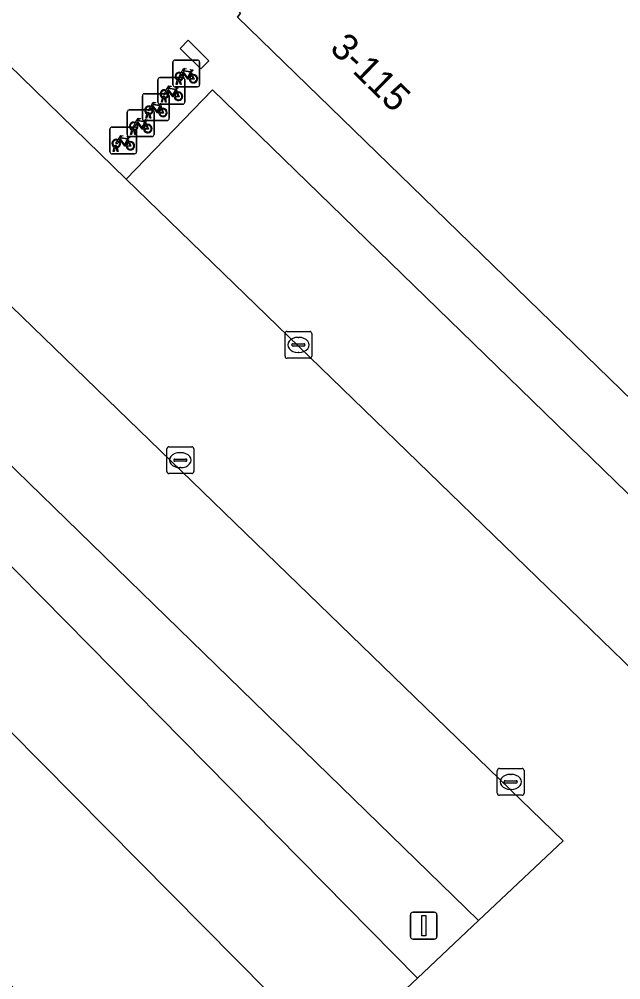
# Model space of a CAD drawing. Extents: x 162344 to 162869, y 381217 to 381818.
# Drawn here: x 162731.05 to 162753.52, y 381504.82 to 381540.68 of the extents above; entities that cross this region are included whole.
import ezdxf

# ---------------------------------------------------------------- set-up
doc = ezdxf.new("R2010")
doc.units = 0
for name, color, linetype in [('IMGEO_Erf', 7, 'Continuous'), ('IMGEO_Fietsenrek', 7, 'Continuous'), ('IMGEO_Groenvoorziening', 7, 'Continuous'), ('IMGEO_Kolk', 7, 'Continuous'), ('IMGEO_Lichtmast', 7, 'Continuous'), ('IMGEO_Pand', 7, 'Continuous'), ('IMGEO_Pand_nummerreeks', 7, 'Continuous'), ('IMGEO_Parkeervlak_open', 7, 'Continuous'), ('IMGEO_Rijbaan_lokaal_open', 7, 'Continuous')]:
    doc.layers.add(name, color=color, linetype=linetype)

msp = doc.modelspace()

# ---------------------------------------------------------------- linework, layer by layer
at = {"layer": 'IMGEO_Erf'}
for points in [[(162701.58, 381592.223), (162697.423, 381587.94), (162694.297, 381584.72), (162697.845, 381581.274), (162694.262, 381577.583), (162691.765, 381574.889), (162691.764, 381574.604), (162695.157, 381571.045), (162696.402, 381572.245), (162698.843, 381569.907), (162702.056, 381573.223), (162726.23, 381549.751), (162723.009, 381546.422), (162723.525, 381545.93), (162729.038, 381540.567), (162729.149, 381540.721), (162730.76, 381539.135), (162730.657, 381538.992), (162735.052, 381534.717), (162738.275, 381538.047), (162760.834, 381516.121)], [(162802.337, 381472.727), (162763.915, 381510.041), (162763.999, 381510.127), (162762.508, 381511.578), (162764.591, 381513.721), (162764.908, 381513.413), (162766.104, 381514.636), (162739.201, 381540.759), (162739.317, 381540.907), (162736.543, 381543.625), (162731.819, 381548.213), (162729.043, 381550.887), (162728.906, 381550.749), (162701.975, 381576.843), (162700.092, 381574.95), (162698.199, 381576.833), (162698.296, 381576.933), (162696.8, 381578.375), (162698.869, 381580.518), (162699.221, 381580.178), (162699.971, 381580.954), (162703.019, 381584.107), (162701.127, 381585.931), (162705.36, 381590.307)]]:
    msp.add_lwpolyline(points, dxfattribs=at)
msp.add_lwpolyline([(162738.136, 381539.135), (162737.841, 381538.836), (162737.069, 381539.597), (162737.358, 381539.902)], close=True, dxfattribs=at)
at = {"layer": 'IMGEO_Fietsenrek'}
for p, q in [((162736.791, 381538.237), (162736.791, 381539.078)), ((162736.791, 381539.078), (162736.791, 381538.237)), ((162736.866, 381539.162), (162737.707, 381539.162)), ((162737.707, 381539.162), (162736.866, 381539.162)), ((162737.791, 381539.087), (162737.791, 381538.246)), ((162737.791, 381538.246), (162737.791, 381539.087)), ((162736.308, 381538.508), (162737.149, 381538.508)), ((162737.149, 381538.508), (162736.308, 381538.508)), ((162737.478, 381538.711), (162737.514, 381538.616)), ((162736.233, 381537.583), (162736.233, 381538.424)), ((162736.233, 381538.424), (162736.233, 381537.583)), ((162737.716, 381538.162), (162736.875, 381538.162)), ((162736.875, 381538.162), (162737.716, 381538.162)), ((162736.918, 381538.246), (162736.957, 381538.406)), ((162736.952, 381538.246), (162736.918, 381538.246)), ((162736.987, 381538.394), (162736.952, 381538.246)), ((162737.029, 381538.418), (162737.028, 381538.422)), ((162737.07, 381538.246), (162737.036, 381538.388)), ((162737.06, 381538.429), (162737.061, 381538.422)), ((162737.068, 381538.392), (162737.103, 381538.246)), ((162737.103, 381538.246), (162737.07, 381538.246)), ((162737.233, 381538.433), (162737.233, 381537.592)), ((162737.233, 381537.592), (162737.233, 381538.433)), ((162735.652, 381536.977), (162735.652, 381537.818)), ((162735.652, 381537.818), (162735.652, 381536.977)), ((162735.727, 381537.902), (162736.568, 381537.902)), ((162736.568, 381537.902), (162735.727, 381537.902)), ((162736.36, 381537.592), (162736.399, 381537.752)), ((162736.429, 381537.74), (162736.394, 381537.592)), ((162736.471, 381537.764), (162736.47, 381537.768)), ((162736.512, 381537.592), (162736.478, 381537.734)), ((162736.502, 381537.775), (162736.503, 381537.768)), ((162736.51, 381537.738), (162736.545, 381537.592)), ((162736.652, 381537.827), (162736.652, 381536.986)), ((162736.652, 381536.986), (162736.652, 381537.827)), ((162736.92, 381538.057), (162736.956, 381537.962)), ((162737.158, 381537.508), (162736.317, 381537.508)), ((162736.317, 381537.508), (162737.158, 381537.508)), ((162736.339, 381537.451), (162736.375, 381537.356)), ((162736.394, 381537.592), (162736.36, 381537.592)), ((162736.545, 381537.592), (162736.512, 381537.592)), ((162735.087, 381536.376), (162735.087, 381537.217)), ((162735.087, 381537.217), (162735.087, 381536.376)), ((162735.162, 381537.301), (162736.003, 381537.301)), ((162736.003, 381537.301), (162735.162, 381537.301)), ((162735.779, 381536.986), (162735.818, 381537.146)), ((162735.848, 381537.134), (162735.813, 381536.986)), ((162735.89, 381537.158), (162735.889, 381537.162)), ((162735.931, 381536.986), (162735.897, 381537.128)), ((162735.921, 381537.169), (162735.922, 381537.162)), ((162735.929, 381537.132), (162735.964, 381536.986)), ((162736.087, 381537.226), (162736.087, 381536.385)), ((162736.087, 381536.385), (162736.087, 381537.226)), ((162734.511, 381536.659), (162735.352, 381536.659)), ((162735.352, 381536.659), (162734.511, 381536.659)), ((162736.577, 381536.902), (162735.736, 381536.902)), ((162735.736, 381536.902), (162736.577, 381536.902)), ((162735.774, 381536.85), (162735.81, 381536.755)), ((162735.813, 381536.986), (162735.779, 381536.986)), ((162735.964, 381536.986), (162735.931, 381536.986)), ((162734.436, 381535.734), (162734.436, 381536.575)), ((162734.436, 381536.575), (162734.436, 381535.734)), ((162736.012, 381536.301), (162735.171, 381536.301)), ((162735.171, 381536.301), (162736.012, 381536.301)), ((162735.214, 381536.385), (162735.253, 381536.545)), ((162735.248, 381536.385), (162735.214, 381536.385)), ((162735.283, 381536.533), (162735.248, 381536.385)), ((162735.325, 381536.557), (162735.324, 381536.561)), ((162735.366, 381536.385), (162735.332, 381536.527)), ((162735.356, 381536.568), (162735.357, 381536.561)), ((162735.364, 381536.531), (162735.399, 381536.385)), ((162735.399, 381536.385), (162735.366, 381536.385)), ((162735.436, 381536.584), (162735.436, 381535.743)), ((162735.436, 381535.743), (162735.436, 381536.584)), ((162735.123, 381536.208), (162735.159, 381536.113)), ((162735.361, 381535.659), (162734.52, 381535.659)), ((162734.52, 381535.659), (162735.361, 381535.659)), ((162734.563, 381535.743), (162734.602, 381535.903)), ((162734.597, 381535.743), (162734.563, 381535.743)), ((162734.632, 381535.891), (162734.597, 381535.743)), ((162734.674, 381535.915), (162734.673, 381535.919)), ((162734.715, 381535.743), (162734.681, 381535.885)), ((162734.705, 381535.926), (162734.706, 381535.919)), ((162734.713, 381535.889), (162734.748, 381535.743)), ((162734.748, 381535.743), (162734.715, 381535.743))]:
    msp.add_line(p, q, dxfattribs=at)
for points in [[(162737.104, 381538.688), (162737.199, 381538.852), (162737.285, 381538.838), (162737.287, 381538.829), (162737.231, 381538.818), (162737.204, 381538.773), (162737.46, 381538.732)], [(162737.46, 381538.732), (162737.485, 381538.781), (162737.479, 381538.785), (162737.456, 381538.789), (162737.444, 381538.796), (162737.443, 381538.799), (162737.445, 381538.804), (162737.54, 381538.789), (162737.542, 381538.779), (162737.532, 381538.766), (162737.52, 381538.76), (162737.506, 381538.766), (162737.478, 381538.711)], [(162737.125, 381538.636), (162737.073, 381538.546), (162737.033, 381538.521), (162737.034, 381538.568), (162737.089, 381538.662)], [(162737.4, 381538.444), (162737.35, 381538.444), (162737.159, 381538.695), (162737.14, 381538.663)], [(162737.447, 381538.707), (162737.19, 381538.748), (162737.173, 381538.719), (162737.34, 381538.499), (162737.447, 381538.707)], [(162737.495, 381538.609), (162737.465, 381538.686), (162737.356, 381538.468), (162737.399, 381538.468)], [(162737.429, 381538.468), (162737.549, 381538.467), (162737.505, 381538.581)], [(162737.525, 381538.588), (162737.58, 381538.443), (162737.43, 381538.443)], [(162736.546, 381538.034), (162736.641, 381538.198), (162736.727, 381538.184), (162736.729, 381538.175), (162736.673, 381538.164), (162736.646, 381538.119), (162736.902, 381538.078)], [(162736.889, 381538.053), (162736.632, 381538.094), (162736.615, 381538.065), (162736.782, 381537.845), (162736.889, 381538.053)], [(162736.902, 381538.078), (162736.927, 381538.127), (162736.921, 381538.131), (162736.898, 381538.135), (162736.886, 381538.142), (162736.885, 381538.145), (162736.887, 381538.15), (162736.982, 381538.135), (162736.984, 381538.125), (162736.974, 381538.112), (162736.962, 381538.106), (162736.948, 381538.112), (162736.92, 381538.057)], [(162736.567, 381537.982), (162736.515, 381537.892), (162736.475, 381537.867), (162736.476, 381537.914), (162736.531, 381538.008)], [(162736.842, 381537.79), (162736.792, 381537.79), (162736.601, 381538.041), (162736.582, 381538.009)], [(162736.937, 381537.955), (162736.907, 381538.032), (162736.798, 381537.814), (162736.841, 381537.814)], [(162736.871, 381537.814), (162736.991, 381537.813), (162736.947, 381537.927)], [(162736.967, 381537.934), (162737.022, 381537.789), (162736.872, 381537.789)], [(162735.986, 381537.376), (162735.934, 381537.286), (162735.894, 381537.261), (162735.895, 381537.308), (162735.95, 381537.402)], [(162735.965, 381537.428), (162736.06, 381537.592), (162736.146, 381537.578), (162736.148, 381537.569), (162736.092, 381537.558), (162736.065, 381537.513), (162736.321, 381537.472)], [(162736.261, 381537.184), (162736.211, 381537.184), (162736.02, 381537.435), (162736.001, 381537.403)], [(162736.308, 381537.447), (162736.051, 381537.488), (162736.034, 381537.459), (162736.201, 381537.239), (162736.308, 381537.447)], [(162736.356, 381537.349), (162736.326, 381537.426), (162736.217, 381537.208), (162736.26, 381537.208)], [(162736.321, 381537.472), (162736.346, 381537.521), (162736.34, 381537.525), (162736.317, 381537.529), (162736.305, 381537.536), (162736.304, 381537.539), (162736.306, 381537.544), (162736.401, 381537.529), (162736.403, 381537.519), (162736.393, 381537.506), (162736.381, 381537.5), (162736.367, 381537.506), (162736.339, 381537.451)], [(162736.29, 381537.208), (162736.41, 381537.207), (162736.366, 381537.321)], [(162736.386, 381537.328), (162736.441, 381537.183), (162736.291, 381537.183)], [(162735.421, 381536.775), (162735.369, 381536.685), (162735.329, 381536.66), (162735.33, 381536.707), (162735.385, 381536.801)], [(162735.4, 381536.827), (162735.495, 381536.991), (162735.581, 381536.977), (162735.583, 381536.968), (162735.527, 381536.957), (162735.5, 381536.912), (162735.756, 381536.871)], [(162735.696, 381536.583), (162735.646, 381536.583), (162735.455, 381536.834), (162735.436, 381536.802)], [(162735.743, 381536.846), (162735.486, 381536.887), (162735.469, 381536.858), (162735.636, 381536.638), (162735.743, 381536.846)], [(162735.791, 381536.748), (162735.761, 381536.825), (162735.652, 381536.607), (162735.695, 381536.607)], [(162735.725, 381536.607), (162735.845, 381536.606), (162735.801, 381536.72)], [(162735.821, 381536.727), (162735.876, 381536.582), (162735.726, 381536.582)], [(162735.756, 381536.871), (162735.781, 381536.92), (162735.775, 381536.924), (162735.752, 381536.928), (162735.74, 381536.935), (162735.739, 381536.938), (162735.741, 381536.943), (162735.836, 381536.928), (162735.838, 381536.918), (162735.828, 381536.905), (162735.816, 381536.899), (162735.802, 381536.905), (162735.774, 381536.85)], [(162734.749, 381536.185), (162734.844, 381536.349), (162734.93, 381536.335), (162734.932, 381536.326), (162734.876, 381536.315), (162734.849, 381536.27), (162735.105, 381536.229)], [(162735.105, 381536.229), (162735.13, 381536.278), (162735.124, 381536.282), (162735.101, 381536.286), (162735.089, 381536.293), (162735.088, 381536.296), (162735.09, 381536.301), (162735.185, 381536.286), (162735.187, 381536.276), (162735.177, 381536.263), (162735.165, 381536.257), (162735.151, 381536.263), (162735.123, 381536.208)], [(162734.77, 381536.133), (162734.718, 381536.043), (162734.678, 381536.018), (162734.679, 381536.065), (162734.734, 381536.159)], [(162735.045, 381535.941), (162734.995, 381535.941), (162734.804, 381536.192), (162734.785, 381536.16)], [(162735.092, 381536.204), (162734.835, 381536.245), (162734.818, 381536.216), (162734.985, 381535.996), (162735.092, 381536.204)], [(162735.14, 381536.106), (162735.11, 381536.183), (162735.001, 381535.965), (162735.044, 381535.965)], [(162735.074, 381535.965), (162735.194, 381535.964), (162735.15, 381536.078)], [(162735.17, 381536.085), (162735.225, 381535.94), (162735.075, 381535.94)]]:
    msp.add_lwpolyline(points, dxfattribs=at)
for centre, radius, start, end in [((162736.869, 381539.084), 0.0779, 92.4484, 184.2845), ((162736.869, 381539.084), 0.0779, 92.4484, 184.2845), ((162737.713, 381539.084), 0.0779, 2.4484, 94.2845), ((162737.713, 381539.084), 0.0779, 2.4484, 94.2845), ((162736.311, 381538.43), 0.0779, 92.4484, 184.2845), ((162736.311, 381538.43), 0.0779, 92.4484, 184.2845), ((162737.031, 381538.547), 0.159, 62.6766, 242.1369), ((162737.031, 381538.547), 0.129, 63.3192, 238.903), ((162737.011, 381538.418), 0.0499, 12.8025, 158.6934), ((162737.031, 381538.547), 0.129, 283.6043, 43.4302), ((162737.031, 381538.547), 0.159, 283.5766, 46.6042), ((162737.155, 381538.43), 0.0779, 2.4484, 94.2845), ((162737.155, 381538.43), 0.0779, 2.4484, 94.2845), ((162737.558, 381538.463), 0.159, 113.3408, 178.3217), ((162737.558, 381538.463), 0.159, 187.0065, 105.7708), ((162737.558, 381538.463), 0.129, 113.923, 177.9556), ((162737.558, 381538.463), 0.129, 188.6715, 104.5883), ((162736.869, 381538.24), 0.0779, 182.4484, 274.2845), ((162736.869, 381538.24), 0.0779, 182.4484, 274.2845), ((162737.031, 381538.547), 0.159, 253.9967, 271.7867), ((162737.011, 381538.418), 0.0174, 12.8025, 163.4502), ((162737.031, 381538.547), 0.129, 253.415, 269.0204), ((162737.713, 381538.24), 0.0779, 272.4484, 4.2845), ((162737.713, 381538.24), 0.0779, 272.4484, 4.2845), ((162735.73, 381537.824), 0.0779, 92.4484, 184.2845), ((162735.73, 381537.824), 0.0779, 92.4484, 184.2845), ((162736.473, 381537.893), 0.159, 62.6766, 242.1369), ((162736.473, 381537.893), 0.129, 63.3192, 238.903), ((162736.453, 381537.764), 0.0499, 12.8025, 158.6934), ((162736.473, 381537.893), 0.159, 253.9967, 271.7867), ((162736.453, 381537.764), 0.0174, 12.8025, 163.4502), ((162736.473, 381537.893), 0.129, 253.415, 269.0204), ((162736.473, 381537.893), 0.129, 283.6043, 43.4302), ((162736.473, 381537.893), 0.159, 283.5766, 46.6042), ((162736.574, 381537.824), 0.0779, 2.4484, 94.2845), ((162736.574, 381537.824), 0.0779, 2.4484, 94.2845), ((162737, 381537.809), 0.159, 113.3408, 178.3217), ((162737, 381537.809), 0.159, 187.0065, 105.7708), ((162737, 381537.809), 0.129, 113.923, 177.9556), ((162737, 381537.809), 0.129, 188.6715, 104.5883), ((162735.892, 381537.287), 0.159, 62.6766, 242.1369), ((162735.892, 381537.287), 0.129, 63.3192, 238.903), ((162735.892, 381537.287), 0.129, 283.6043, 43.4302), ((162735.892, 381537.287), 0.159, 283.5766, 46.6042), ((162736.311, 381537.586), 0.0779, 182.4484, 274.2845), ((162736.311, 381537.586), 0.0779, 182.4484, 274.2845), ((162737.155, 381537.586), 0.0779, 272.4484, 4.2845), ((162737.155, 381537.586), 0.0779, 272.4484, 4.2845), ((162735.165, 381537.223), 0.0779, 92.4484, 184.2845), ((162735.165, 381537.223), 0.0779, 92.4484, 184.2845), ((162735.872, 381537.158), 0.0499, 12.8025, 158.6934), ((162735.892, 381537.287), 0.159, 253.9967, 271.7867), ((162735.872, 381537.158), 0.0174, 12.8025, 163.4502), ((162735.892, 381537.287), 0.129, 253.415, 269.0204), ((162736.009, 381537.223), 0.0779, 2.4484, 94.2845), ((162736.009, 381537.223), 0.0779, 2.4484, 94.2845), ((162736.419, 381537.203), 0.159, 113.3408, 178.3217), ((162736.419, 381537.203), 0.159, 187.0065, 105.7708), ((162736.419, 381537.203), 0.129, 113.923, 177.9556), ((162736.419, 381537.203), 0.129, 188.6715, 104.5883), ((162734.514, 381536.581), 0.0779, 92.4484, 184.2845), ((162734.514, 381536.581), 0.0779, 92.4484, 184.2845), ((162735.327, 381536.686), 0.159, 62.6766, 242.1369), ((162735.327, 381536.686), 0.129, 63.3192, 238.903), ((162735.358, 381536.581), 0.0779, 2.4484, 94.2845), ((162735.358, 381536.581), 0.0779, 2.4484, 94.2845), ((162735.327, 381536.686), 0.129, 283.6043, 43.4302), ((162735.327, 381536.686), 0.159, 283.5766, 46.6042), ((162735.73, 381536.98), 0.0779, 182.4484, 274.2845), ((162735.73, 381536.98), 0.0779, 182.4484, 274.2845), ((162735.854, 381536.602), 0.159, 113.3408, 178.3217), ((162735.854, 381536.602), 0.159, 187.0065, 105.7708), ((162735.854, 381536.602), 0.129, 113.923, 177.9556), ((162735.854, 381536.602), 0.129, 188.6715, 104.5883), ((162736.574, 381536.98), 0.0779, 272.4484, 4.2845), ((162736.574, 381536.98), 0.0779, 272.4484, 4.2845), ((162735.165, 381536.379), 0.0779, 182.4484, 274.2845), ((162735.165, 381536.379), 0.0779, 182.4484, 274.2845), ((162735.307, 381536.557), 0.0499, 12.8025, 158.6934), ((162735.327, 381536.686), 0.159, 253.9967, 271.7867), ((162735.307, 381536.557), 0.0174, 12.8025, 163.4502), ((162735.327, 381536.686), 0.129, 253.415, 269.0204), ((162736.009, 381536.379), 0.0779, 272.4484, 4.2845), ((162736.009, 381536.379), 0.0779, 272.4484, 4.2845), ((162734.676, 381536.044), 0.159, 62.6766, 242.1369), ((162734.676, 381536.044), 0.129, 63.3192, 238.903), ((162734.656, 381535.915), 0.0499, 12.8025, 158.6934), ((162734.676, 381536.044), 0.129, 283.6043, 43.4302), ((162734.676, 381536.044), 0.159, 283.5766, 46.6042), ((162735.203, 381535.96), 0.159, 113.3408, 178.3217), ((162735.203, 381535.96), 0.159, 187.0065, 105.7708), ((162735.203, 381535.96), 0.129, 113.923, 177.9556), ((162735.203, 381535.96), 0.129, 188.6715, 104.5883), ((162734.514, 381535.737), 0.0779, 182.4484, 274.2845), ((162734.514, 381535.737), 0.0779, 182.4484, 274.2845), ((162734.676, 381536.044), 0.159, 253.9967, 271.7867), ((162734.656, 381535.915), 0.0174, 12.8025, 163.4502), ((162734.676, 381536.044), 0.129, 253.415, 269.0204), ((162735.358, 381535.737), 0.0779, 272.4484, 4.2845), ((162735.358, 381535.737), 0.0779, 272.4484, 4.2845)]:
    msp.add_arc(centre, radius, start, end, dxfattribs=at)
at = {"layer": 'IMGEO_Groenvoorziening'}
msp.add_lwpolyline([(162745.929, 381504.89), (162748.205, 381507.033), (162727.21, 381527.46), (162725.764, 381525.323)], close=True, dxfattribs=at)
at = {"layer": 'IMGEO_Kolk'}
for p, q in [((162740.978, 381528.101), (162740.978, 381528.953)), ((162741.053, 381529.027), (162741.905, 381529.027)), ((162741.466, 381528.807), (162741.491, 381528.807)), ((162741.979, 381528.953), (162741.979, 381528.101)), ((162741.237, 381528.521), (162741.237, 381528.533)), ((162741.675, 381528.484), (162741.277, 381528.484)), ((162741.28, 381528.57), (162741.678, 381528.57)), ((162741.721, 381528.533), (162741.721, 381528.521)), ((162741.489, 381528.247), (162741.464, 381528.247)), ((162741.905, 381528.027), (162741.053, 381528.027)), ((162736.568, 381523.797), (162736.568, 381524.649)), ((162736.643, 381524.723), (162737.495, 381524.723)), ((162737.056, 381524.503), (162737.081, 381524.503)), ((162737.569, 381524.649), (162737.569, 381523.797)), ((162736.827, 381524.217), (162736.827, 381524.229)), ((162737.265, 381524.18), (162736.867, 381524.18)), ((162736.87, 381524.266), (162737.268, 381524.266)), ((162737.311, 381524.229), (162737.311, 381524.217)), ((162737.079, 381523.943), (162737.054, 381523.943)), ((162737.495, 381523.723), (162736.643, 381523.723)), ((162748.907, 381511.787), (162748.907, 381512.639)), ((162748.982, 381512.713), (162749.834, 381512.713)), ((162749.908, 381512.639), (162749.908, 381511.787)), ((162749.395, 381512.493), (162749.42, 381512.493)), ((162749.166, 381512.207), (162749.166, 381512.219)), ((162749.604, 381512.17), (162749.206, 381512.17)), ((162749.209, 381512.256), (162749.607, 381512.256)), ((162749.418, 381511.933), (162749.393, 381511.933)), ((162749.65, 381512.219), (162749.65, 381512.207)), ((162749.834, 381511.713), (162748.982, 381511.713))]:
    msp.add_line(p, q, dxfattribs=at)
for points in [[(162740.978, 381528.101), (162740.978, 381528.953)], [(162741.053, 381529.027), (162741.905, 381529.027)], [(162741.979, 381528.953), (162741.979, 381528.101)], [(162741.905, 381528.027), (162741.053, 381528.027)], [(162736.568, 381523.797), (162736.568, 381524.649)], [(162736.643, 381524.723), (162737.495, 381524.723)], [(162737.569, 381524.649), (162737.569, 381523.797)], [(162737.495, 381523.723), (162736.643, 381523.723)], [(162748.907, 381511.787), (162748.907, 381512.639)], [(162748.982, 381512.713), (162749.834, 381512.713)], [(162749.908, 381512.639), (162749.908, 381511.787)], [(162749.834, 381511.713), (162748.982, 381511.713)]]:
    msp.add_lwpolyline(points, dxfattribs=at)
for centre, radius, start, end in [((162741.055, 381528.951), 0.0765, 91.552, 178.448), ((162741.055, 381528.951), 0.0765, 91.552, 178.448), ((162741.903, 381528.951), 0.0765, 1.552, 88.448), ((162741.903, 381528.951), 0.0765, 1.552, 88.448), ((162741.277, 381528.53), 0.0403, 85.8775, 175.7526), ((162741.274, 381528.52), 0.0366, 178.938, 274.7102), ((162741.678, 381528.527), 0.043, 264.8664, 352.4533), ((162741.682, 381528.532), 0.0386, 1.7309, 96.639), ((162741.055, 381528.103), 0.0765, 181.552, 268.448), ((162741.055, 381528.103), 0.0765, 181.552, 268.448), ((162741.903, 381528.103), 0.0765, 271.552, 358.448), ((162741.903, 381528.103), 0.0765, 271.552, 358.448), ((162736.645, 381524.647), 0.0765, 91.552, 178.448), ((162736.645, 381524.647), 0.0765, 91.552, 178.448), ((162737.493, 381524.647), 0.0765, 1.552, 88.448), ((162737.493, 381524.647), 0.0765, 1.552, 88.448), ((162736.867, 381524.226), 0.0403, 85.8775, 175.7526), ((162736.864, 381524.216), 0.0366, 178.938, 274.7102), ((162737.268, 381524.223), 0.043, 264.8664, 352.4533), ((162737.272, 381524.228), 0.0386, 1.7309, 96.639), ((162736.645, 381523.799), 0.0765, 181.552, 268.448), ((162736.645, 381523.799), 0.0765, 181.552, 268.448), ((162737.493, 381523.799), 0.0765, 271.552, 358.448), ((162737.493, 381523.799), 0.0765, 271.552, 358.448), ((162748.984, 381512.637), 0.0765, 91.552, 178.448), ((162748.984, 381512.637), 0.0765, 91.552, 178.448), ((162749.832, 381512.637), 0.0765, 1.552, 88.448), ((162749.832, 381512.637), 0.0765, 1.552, 88.448), ((162749.206, 381512.216), 0.0403, 85.8775, 175.7526), ((162749.203, 381512.206), 0.0366, 178.938, 274.7102), ((162749.607, 381512.213), 0.043, 264.8664, 352.4533), ((162749.611, 381512.218), 0.0386, 1.7309, 96.639), ((162748.984, 381511.789), 0.0765, 181.552, 268.448), ((162748.984, 381511.789), 0.0765, 181.552, 268.448), ((162749.832, 381511.789), 0.0765, 271.552, 358.448), ((162749.832, 381511.789), 0.0765, 271.552, 358.448)]:
    msp.add_arc(centre, radius, start, end, dxfattribs=at)
for centre, major_axis, ratio, start_param, end_param in [((162741.465, 381528.527), (-0.387, 0.002), 0.722429, 4.712389, 7.853982), ((162741.49, 381528.527), (-0.39, 0.002), 0.717154, 1.570796, 4.712389), ((162737.055, 381524.223), (-0.387, 0.002), 0.722429, 4.712389, 7.853982), ((162737.08, 381524.223), (-0.39, 0.002), 0.717154, 1.570796, 4.712389), ((162749.394, 381512.213), (-0.387, 0.002), 0.722429, 4.712389, 7.853982), ((162749.419, 381512.213), (-0.39, 0.002), 0.717154, 1.570796, 4.712389)]:
    msp.add_ellipse(centre, major_axis=major_axis, ratio=ratio, start_param=start_param, end_param=end_param, dxfattribs=at)
at = {"layer": 'IMGEO_Lichtmast'}
for p, q in [((162745.762, 381507.345), (162746.552, 381507.345)), ((162746.552, 381507.345), (162745.762, 381507.345)), ((162745.662, 381506.445), (162745.662, 381507.245)), ((162745.662, 381507.245), (162745.662, 381506.445)), ((162746.652, 381507.245), (162746.652, 381506.445)), ((162746.652, 381506.445), (162746.652, 381507.245)), ((162746.552, 381506.345), (162745.762, 381506.345)), ((162745.762, 381506.345), (162746.552, 381506.345))]:
    msp.add_line(p, q, dxfattribs=at)
msp.add_lwpolyline([(162746.082, 381507.22), (162746.232, 381507.22), (162746.232, 381506.47), (162746.082, 381506.47), (162746.082, 381507.22)], dxfattribs=at)
for centre, start, end in [((162745.762, 381507.245), 90, 180), ((162745.762, 381507.245), 90, 180), ((162746.552, 381507.245), 0, 90), ((162746.552, 381507.245), 360, 90), ((162745.762, 381506.445), 180, 270), ((162745.762, 381506.445), 180, 270), ((162746.552, 381506.445), 270, 0), ((162746.552, 381506.445), 270, 0)]:
    msp.add_arc(centre, 0.1, start, end, dxfattribs=at)
at = {"layer": 'IMGEO_Pand'}
msp.add_lwpolyline([(162756.753, 381572.671), (162744.14, 381555.44), (162742.025, 381552.551), (162742.712, 381552.068), (162736.543, 381543.625), (162739.317, 381540.907), (162739.201, 381540.759), (162766.104, 381514.636)], dxfattribs=at)
msp.add_lwpolyline([(162737.358, 381539.902), (162737.069, 381539.597), (162737.841, 381538.836), (162738.136, 381539.135)], close=True, dxfattribs=at)
at = {"layer": 'IMGEO_Parkeervlak_open'}
for points in [[(162738.275, 381538.047), (162735.052, 381534.717), (162757.648, 381512.81), (162760.834, 381516.121)], [(162727.593, 381533.024), (162726.733, 381531.836), (162729.06, 381530.149), (162723.591, 381522.638), (162721.286, 381524.312), (162720.995, 381523.911), (162742.775, 381501.923), (162745.929, 381504.89), (162725.764, 381525.323), (162727.21, 381527.46), (162748.205, 381507.033), (162751.368, 381510.009)]]:
    msp.add_lwpolyline(points, close=True, dxfattribs=at)
at = {"layer": 'IMGEO_Rijbaan_lokaal_open'}
msp.add_lwpolyline([(162797.018, 381475.544), (162761.683, 381509.813), (162757.977, 381512.47), (162757.648, 381512.81), (162735.052, 381534.717), (162730.657, 381538.992), (162726.872, 381533.722), (162727.593, 381533.024), (162751.368, 381510.009), (162748.205, 381507.033), (162745.929, 381504.89), (162742.775, 381501.923), (162720.995, 381523.911), (162720.297, 381524.616), (162716.345, 381519.097), (162717.053, 381518.385), (162737.94, 381497.381)], dxfattribs=at)

# ---------------------------------------------------------------- texts
at = {"layer": 'IMGEO_Pand_nummerreeks'}
msp.add_text('3-115', height=1, rotation=315.6473, dxfattribs=at).set_placement((162742.611, 381539.55))

doc.saveas('drawing.dxf')
